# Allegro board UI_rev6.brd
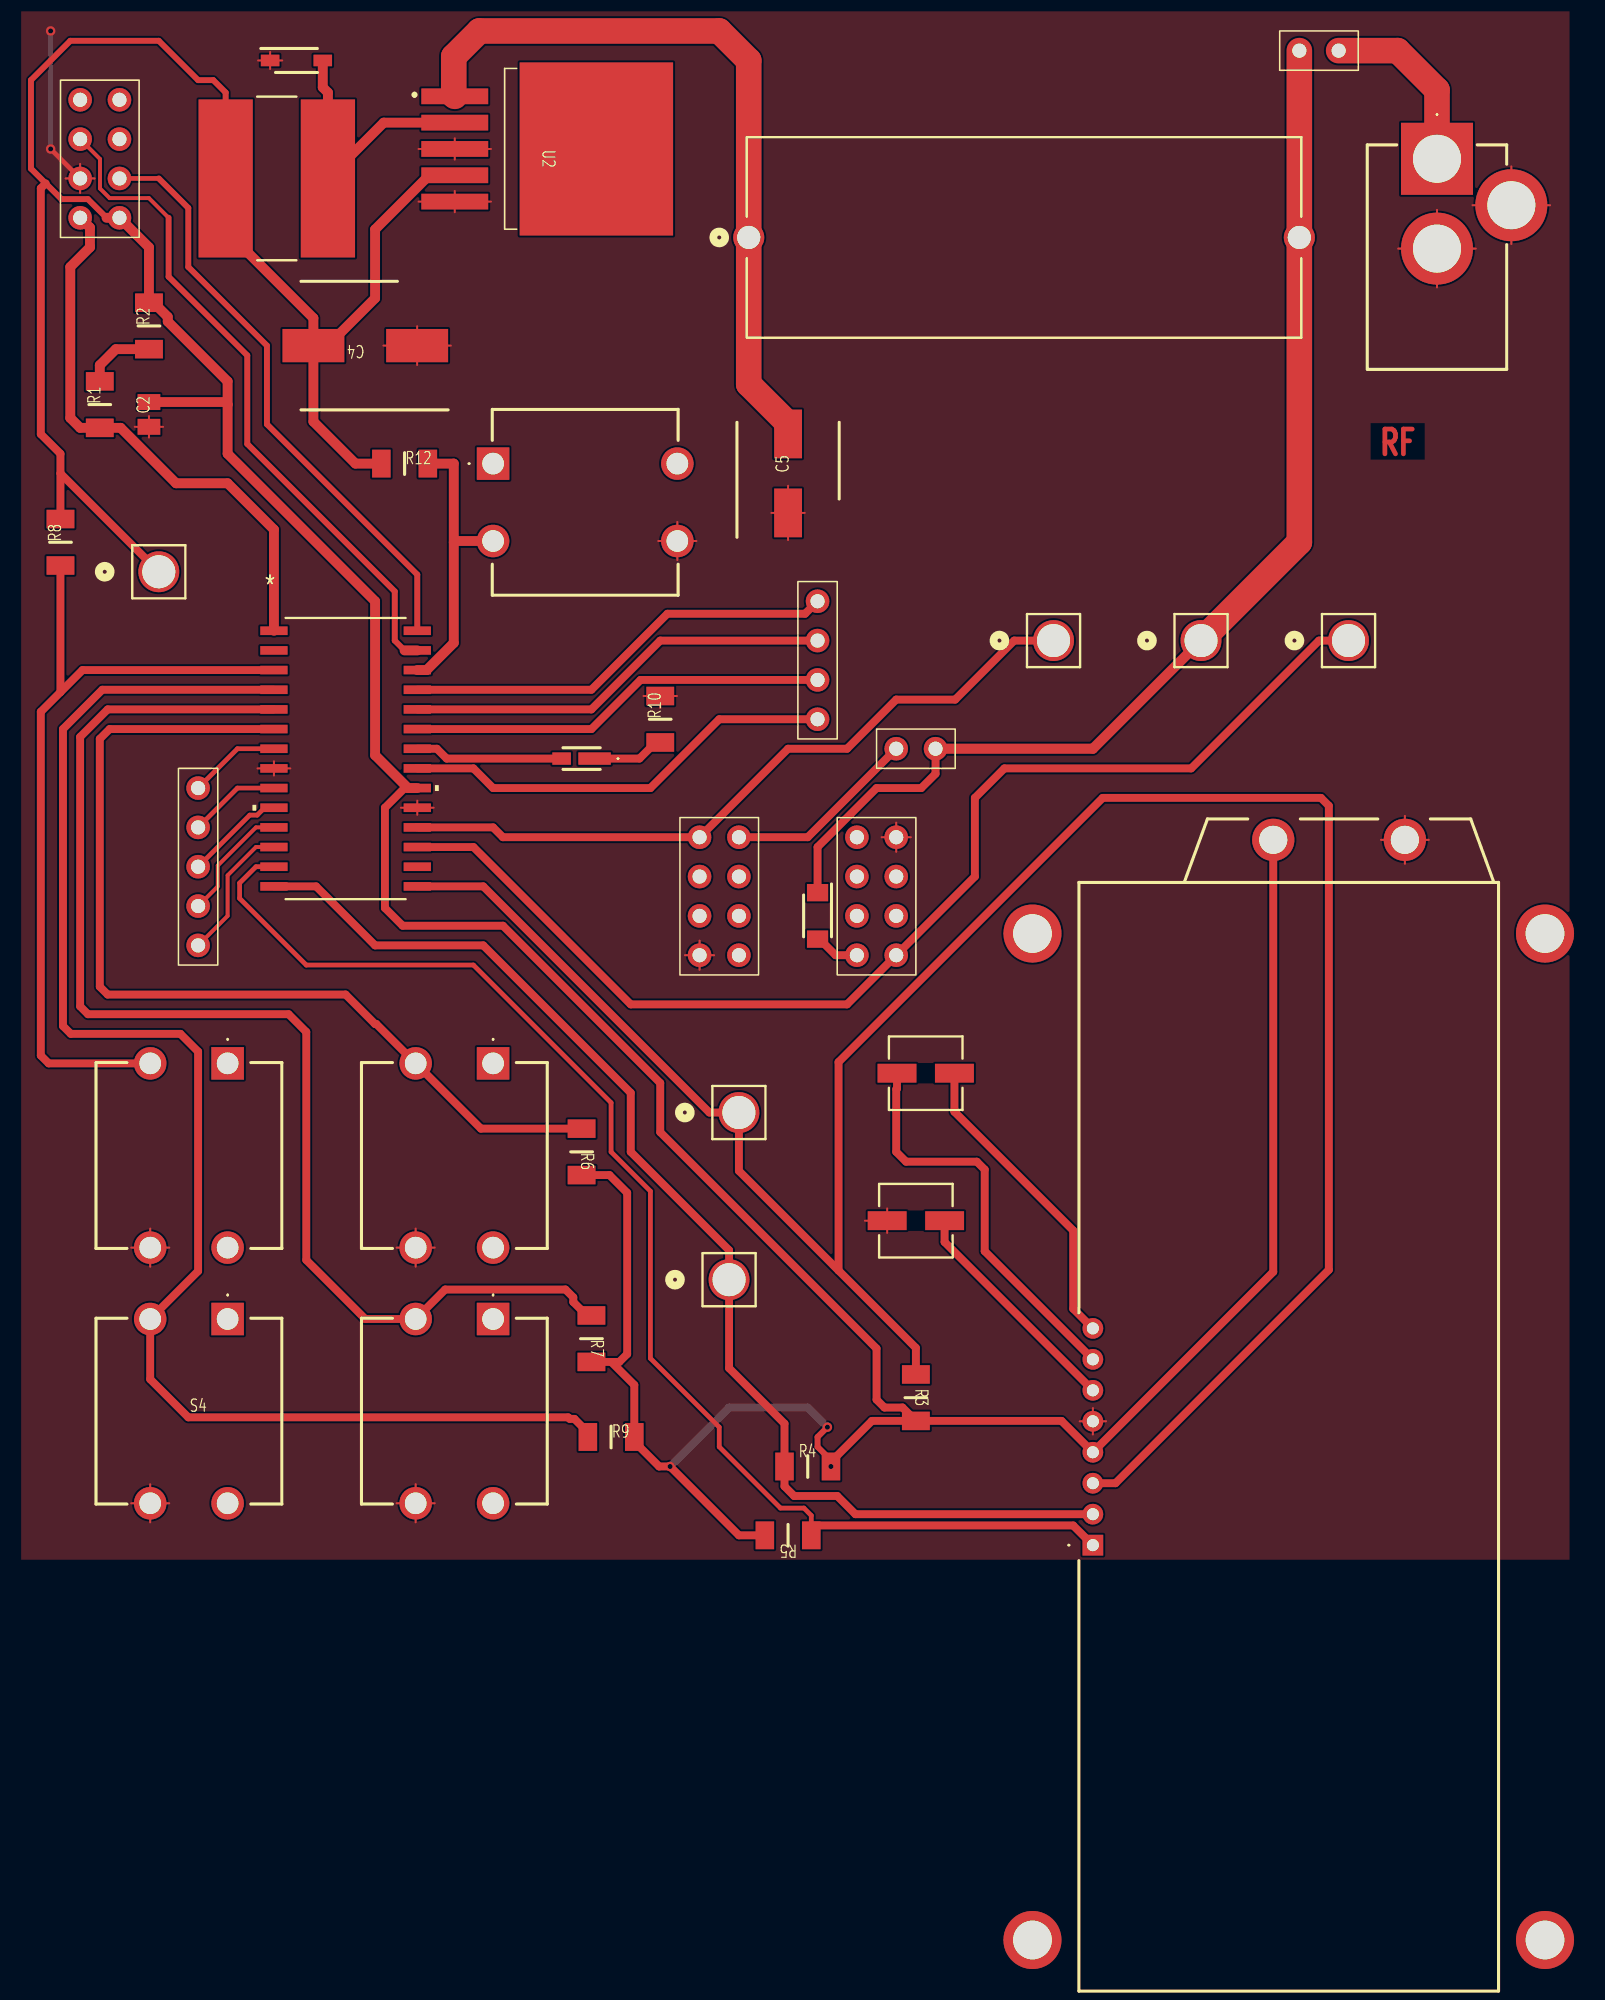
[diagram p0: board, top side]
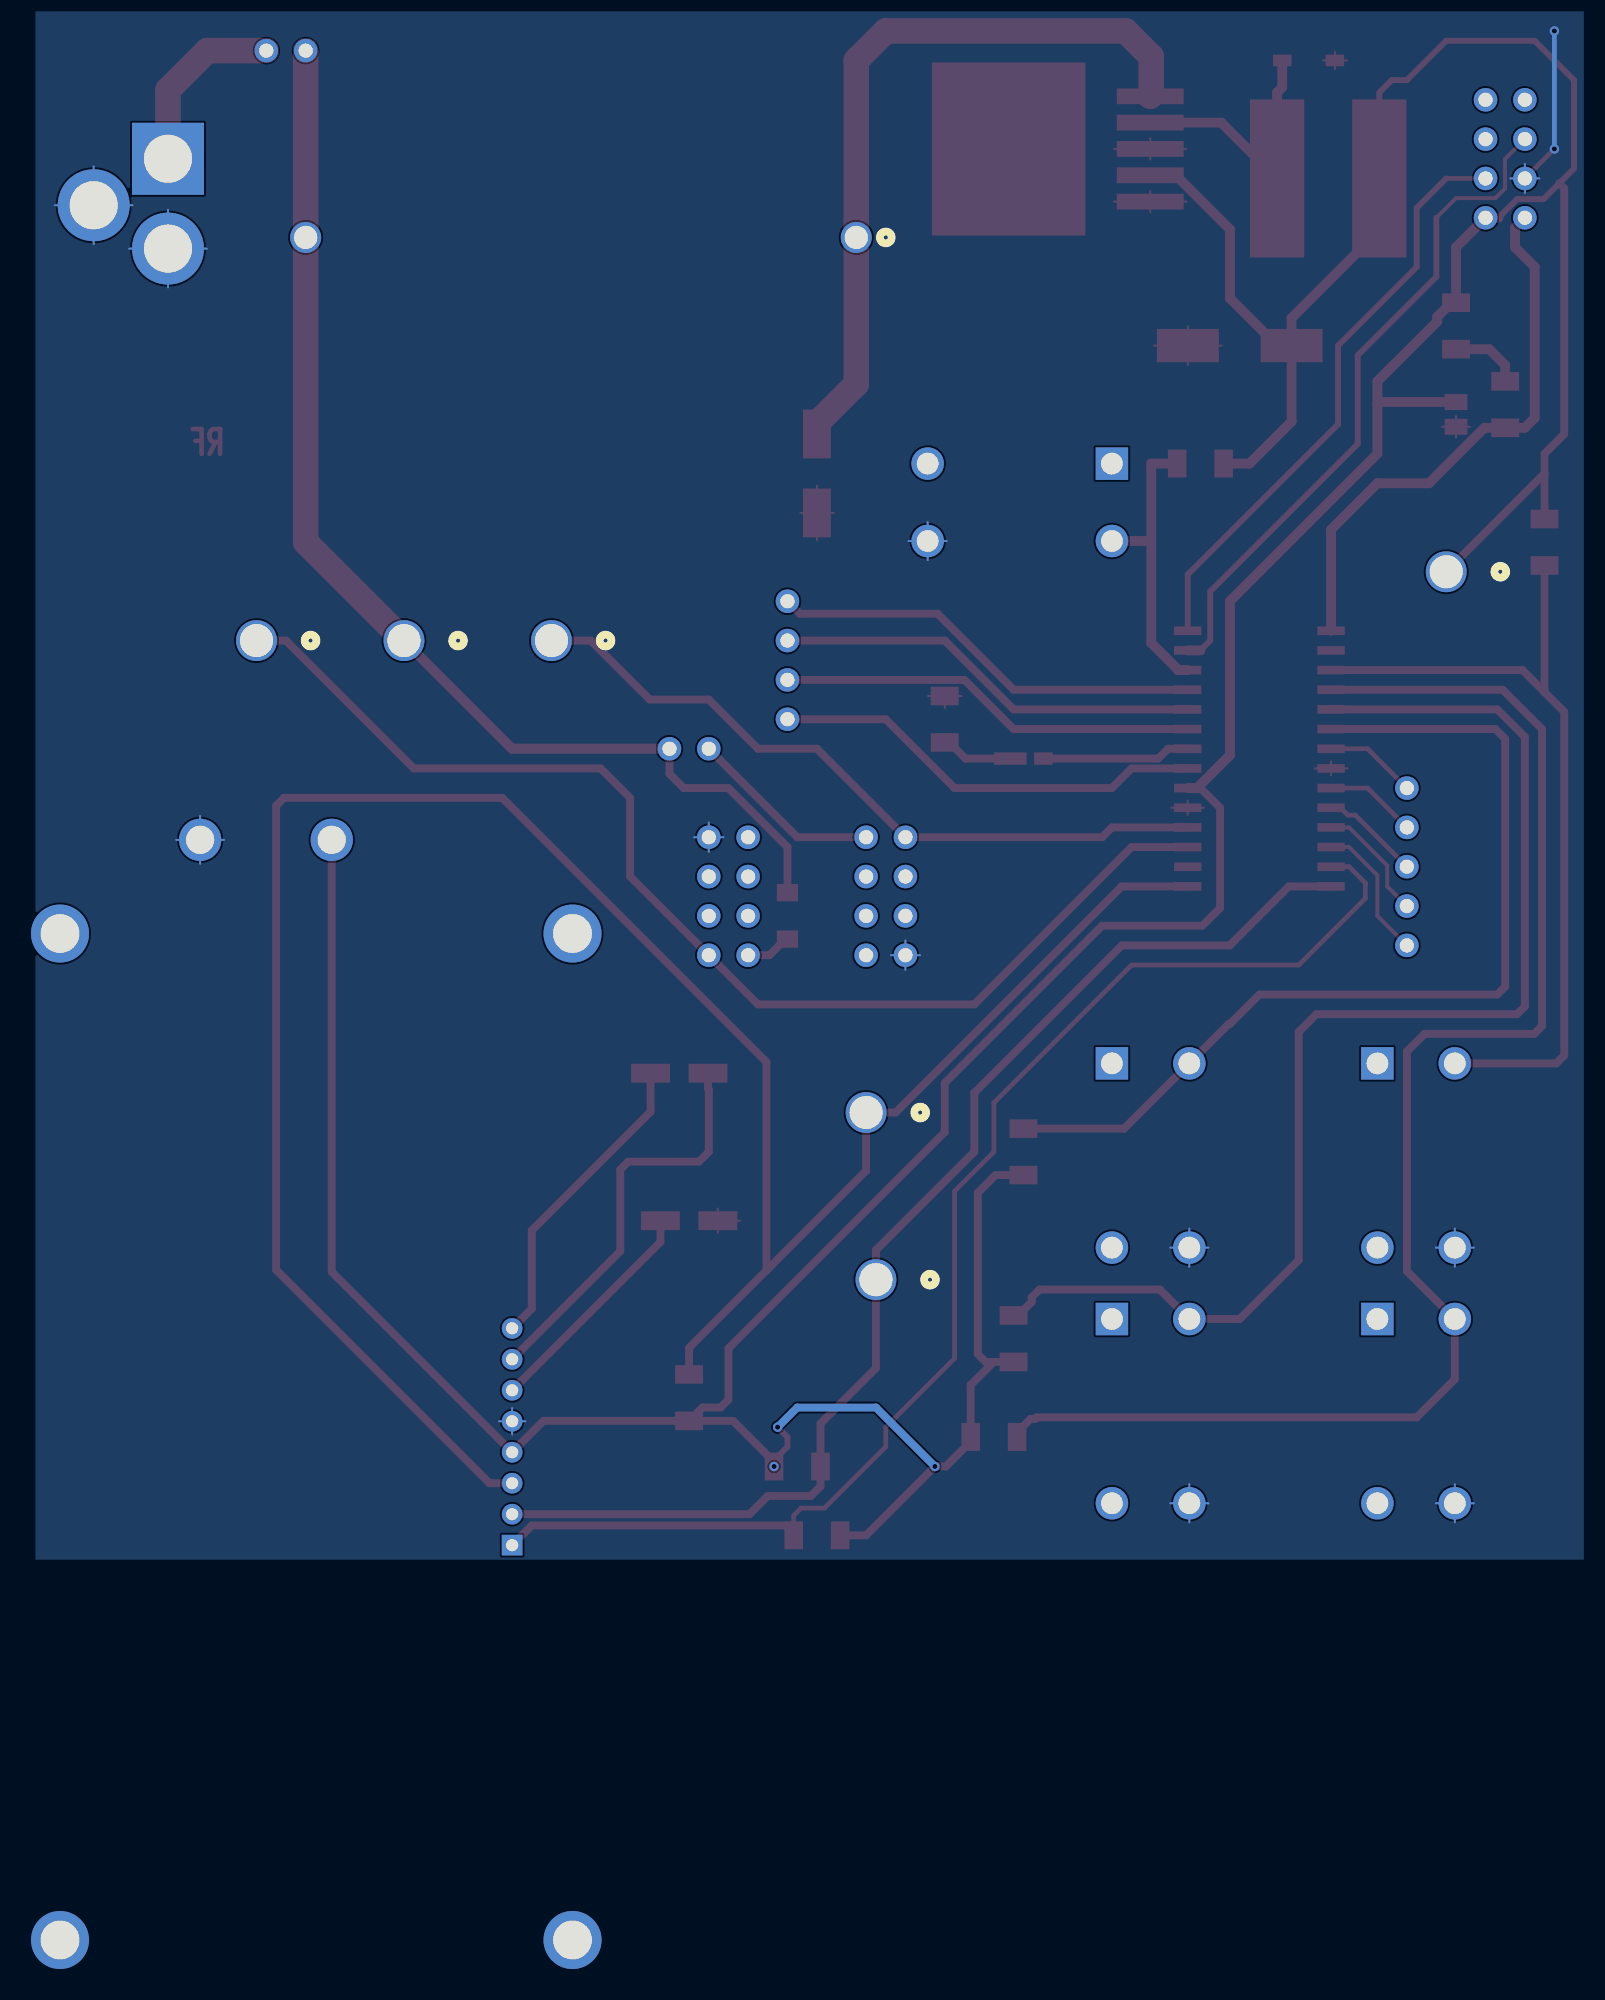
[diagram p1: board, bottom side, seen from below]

No outline. copper layers: TOP, BOTTOM. Coordinates in mm from the lowest, leftmost part position.

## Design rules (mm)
constraint set DEFAULT: min track width 0.127

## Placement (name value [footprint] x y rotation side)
C1  1uF  [CAP_WCAP-ASLI_04P0X05P5_WRE]  55.25 20.95 0 top
C2  0.1uF  [CAPC2012X147N]  5.71 73.02 90 top
C3  1uF  [CAP_WCAP-ASLI_04P0X05P5_WRE]  55.88 30.48 0 top
C4  330uF  [CAPAE830X1050N]  19.69 77.47 180 top
C5  100uF  [CAPAE660X770N]  46.99 69.21 90 top
D1  1N5819  [SOD3716X145N]  15.24 95.88 0 top
D2  LED  [T1341NB30C000112U1930]  33.65 50.8 270 top
D3  SBR3U40S1F-7  [SODFL3518X115N]  48.89 40.64 270 top
DS1  NHD-C0220BIZ-FSW-FBW-3V3M  [NHDC0220BIZFSWFBW3V3M]  66.68 0 270 top
F1  500mA  [FUSE_354101-GY_LTF]  44.45 84.45 0 top
J2  8 HEADER- Snapmaker Debugger  [JUMPER8]  1.27 85.72 0 top
J4  Daisy In  [JUMPER8]  43.81 45.72 180 top
J5  Daisy Out  [JUMPER8]  51.44 38.1 0 top
J6  CON4  [JUMPER4]  48.89 53.34 90 top
J8  JUMPER  [JUMPER2]  56.51 51.44 180 top
J9  JUMPER  [JUMPER2]  80.01 96.52 0 top
J10  CON5  [JUMPER5]  8.89 48.89 270 top
L1  220 uH  [IND_BOURNS_SRN1060]  13.97 88.26 0 top
P1  CONN JACK PWR  [694108301002]  88.9 89.53 90 top
R1  220  [RESC3216X75N]  2.54 73.66 90 top
R2  1K  [RESC3216X75N]  5.71 78.74 90 top
R3  10K  [RESC3216X75N]  55.25 9.52 270 top
R4  10K  [RESC3216X75N]  48.26 5.08 0 top
R5  10K  [RESC3216X75N]  46.99 0.63 180 top
R6  10K  [RESC3216X75N]  33.65 25.4 270 top
R7  10K  [RESC3216X75N]  34.29 13.33 270 top
R8  10K  [RESC3216X75N]  0 64.77 90 top
R9  10K  [RESC3216X75N]  35.56 6.98 0 top
R10  1K  [RESC3216X75N]  38.73 53.34 90 top
R12  10K  [RESC3216X75N]  22.22 69.85 0 top
S1  PRT-14460  [PRT14460]  10.79 31.11 0 top
S2  PRT-14460  [PRT14460]  27.94 14.6 0 top
S3  PRT-14460  [PRT14460]  27.94 31.11 0 top
S4  PRT-14460  [PRT14460]  10.79 14.6 0 top
S6  PRT-14460  [PRT14460]  27.94 69.85 90 top
TP1  TEST POINT  [CONN1_5011_KEY]  6.35 62.86 0 top
TP2  TEST POINT  [CONN1_5011_KEY]  73.66 58.42 0 top
TP3  TEST POINT  [CONN1_5011_KEY]  43.81 27.94 0 top
TP4  TEST POINT  [CONN1_5011_KEY]  43.18 17.14 0 top
TP5  TEST POINT  [CONN1_5011_KEY]  83.19 58.42 0 top
TP6  TEST POINT  [CONN1_5011_KEY]  64.13 58.42 0 top
U2  LM2575-3P3WU-TR  [MIC29302WU]  37.46 90.17 270 top
U3  PIC18F27Q10-SPSOSS  [SOIC28_SO_MCH]  18.41 50.8 0 top

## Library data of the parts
C1 C3 = C: User Part Number: PN; Tolerance: TOL
C2 C4 C5 = C
D1 = DIODE SCHOTTKY
D2 = LED
D3 = SBR3U40S1F-7
DS1 = NHD-C0220BIZ-FSW-FBW-3V3M
F1 = FUSE: User Part Number: PN; Tolerance: TOL
J2 = 8 HEADER: User Part Number: ***
J4 J5 = CON8: User Part Number: ***
J6 = CON4: User Part Number: ***
J8 J9 = JUMPER: User Part Number: ***
J10 = CON5: User Part Number: ***
L1 = INDUCTOR: User Part Number: PN; Tolerance: TOL
P1 = CONN JACK PWR
R1-R10 R12 = RESISTOR
S1-S4 S6 = PRT-14460
TP1-TP6 = TEST POINT: User Part Number: PN; Tolerance: TOL
U2 = LM2575-3P3WU-TR_2
U3 = PIC18F27Q10T-ISO: User Part Number: PN; Tolerance: TOL

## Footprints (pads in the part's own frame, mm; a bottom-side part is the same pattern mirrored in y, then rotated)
694108301002
  rect 4.65x4.65 hole 3.1: 1(0,0)
  round 4.65 hole 3.1: 2(-5.8,0) 3(-3,-4.8)
CAP_WCAP-ASLI_04P0X05P5_WRE
  rect 2.515x1.219 smd: 1(-1.854,0) 2(1.854,0)
CAPAE660X770N
  rect 3.15x1.8 smd: 1(-2.55,0) 2(2.55,0)
CAPAE830X1050N
  rect 4x2.15 smd: 1(-3.35,0) 2(3.35,0)
CAPC2012X147N
  rect 1.03x1.47 smd: 1(-0.8,0) 2(0.8,0)
CONN1_5011_KEY
  round 2.642 hole 2.134: 1(0,0)
FUSE_354101-GY_LTF
  round 2.007 hole 1.499: 1(0,0) 2(35.56,0)
IND_BOURNS_SRN1060
  rect 3.505x10.211 smd: 1(-3.302,0) 2(3.302,0)
JUMPER2
  round 1.524 hole 0.914: 1(0,0) 2(2.54,0)
JUMPER4
  round 1.524 hole 0.914: 1(0,0) 2(2.54,0) 3(5.08,0) 4(7.62,0)
JUMPER5
  round 1.524 hole 0.914: 1(0,0) 2(2.54,0) 3(5.08,0) 4(7.62,0) 5(10.16,0)
JUMPER8
  round 1.524 hole 0.914: 1(0,0) 2(2.54,0) 3(0,2.54) 4(2.54,2.54) 5(0,5.08) 6(2.54,5.08) 7(0,7.62) 8(2.54,7.62)
MIC29302WU
  rect 1.02x4.32 smd: 1(-3.4,-12) 2(-1.7,-12) 3(0,-12) 4(1.7,-12) 5(3.4,-12)
  rect 11.18x9.91 smd: 6(0,-2.855)
NHDC0220BIZFSWFBW3V3M
  rect 1.337x1.337 hole 0.78: 1(0,0)
  round 1.337 hole 0.78: 2(-2,0) 3(-4,0) 4(-6,0) 5(-8,0) 6(-10,0) 7(-12,0) 8(-14,0)
  round 2.73 hole 1.82: 9(-45.55,20.15) 10(-45.55,11.65)
  round 3.75 hole 2.5: 11(25.5,-3.9) 12(-39.5,-3.9) 13(25.5,29.2) 14(-39.5,29.2)
PRT14460
  rect 2.1x2.1 hole 1.4: 1(0,0)
  round 2.1 hole 1.4: 2(0,-11.9) 3(-5,0) 4(-5,-11.9)
RESC3216X75N
  rect 1.2x1.8 smd: 1(-1.5,0) 2(1.5,0)
SOD3716X145N
  rect 1.2x0.75 smd: 1(-1.7,0) 2(1.7,0)
SODFL3518X115N
  rect 1.12x1.37 smd: 1(-1.5,0) 2(1.5,0)
SOIC28_SO_MCH
  rect 1.765x0.559 smd: 1(-4.629,8.255) 2(-4.629,6.985) 3(-4.629,5.715) 4(-4.629,4.445) 5(-4.629,3.175) 6(-4.629,1.905) 7(-4.629,0.635) 8(-4.629,-0.635) 9(-4.629,-1.905) 10(-4.629,-3.175) 11(-4.629,-4.445) 12(-4.629,-5.715) 13(-4.629,-6.985) 14(-4.629,-8.255) 15(4.629,-8.255) 16(4.629,-6.985) 17(4.629,-5.715) 18(4.629,-4.445) 19(4.629,-3.175) 20(4.629,-1.905) 21(4.629,-0.635) 22(4.629,0.635) 23(4.629,1.905) 24(4.629,3.175) 25(4.629,4.445) 26(4.629,5.715) 27(4.629,6.985) 28(4.629,8.255)
T1341NB30C000112U1930
  rect 0.8x2.1 smd: 1(0,0.84)
  rect 0.8x1.2 smd: 2(0,-1.29)

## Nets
+3.3V: C2.2 C4.2 DS1.4(VSS) DS1.10 J2.2 L1.1 R2.2 R3.2 R4.2 R5.2 R6.2 R7.2 R8.2 R9.2 R12.1 TP1.1 U2.4 U3.20
GND: C1.1 C2.1 C4.1 C5.1 D1.1 DS1.5 DS1.9 J2.3 J4.8 J5.8 P1.2 P1.3 R10.2 S1.4 S2.4 S3.4 S4.4 S6.4 U2.3 U2.5 U3.8 U3.19(VSS_2)
ICSPCLK: J2.5 U3.27
ICSPDAT: J2.4 U3.28
LEFTBUTTON: R6.1 S3.3 U3.6
MCLR: J2.1 R1.1 U3.1
PWR IN: J4.1 J8.2
PWR OUT: D3.1(K) F1.2 J8.1 J9.1 TP2.1
RA5: J10.1 U3.7
RA6: J10.3 U3.10
RA7: J10.2 U3.9
RB0: J6.1 U3.21
RB2: J6.2 U3.23
RB3: J6.3 U3.24
RB4: J6.4 U3.25
RB5: R12.2 S6.3 U3.26
RC0: J10.4 U3.11
RC1: J10.5 U3.12
RIGHTBUTTON: R7.1 S2.3 U3.5
RST: DS1.1 R5.1 U3.13
RX: J4.2 TP6.1 U3.18
SCL: DS1.2 R4.1 TP4.1 U3.14
SDA: DS1.3 R3.1 TP3.1 U3.15
SELECT1: R8.1 S1.3 U3.3
SELECT2: R9.1 S4.3 U3.4
TX: J5.2 TP5.1 U3.17
N01597: R1.2 R2.1
N05849: D1.2(CATHODE) L1.2 U2.2
N06927: C5.2 F1.1 U2.1(VIN)
N30188: D2.1(CATHODE) R10.1
N40798: C1.2 DS1.6
N40848: C3.1 DS1.7
N40866: C3.2 DS1.8
N41411: J9.2 P1.1
N115890: D2.2 U3.22
N187930: D3.2 J5.1

Pads without a net: DS1 11 12 13 14; J2 6 7 8; J4 3 4 5 6 7; J5 3 4 5 6 7; S1 1 2; S2 1 2; S3 1 2; S4 1 2; S6 1 2; U2 6; U3 2 16

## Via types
v1: diameter 0.61, hole 0.33, TOP to BOTTOM, 5 vias

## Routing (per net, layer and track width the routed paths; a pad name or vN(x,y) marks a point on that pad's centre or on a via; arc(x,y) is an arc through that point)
+3.3V: length 326.9
  TOP w0.381: 2.98,85.72 1.77,86.93 0.06,86.93 -1.91,88.9 -1.91,94.62 0.63,97.15 6.35,97.15 8.89,94.62 9.87,94.62 10.67,93.81 L1.1 ; 49.76,5.38 49.76,5.48 48.89,6.35 48.89,6.98 v1(49.53,7.62)
  TOP w0.508: R3.2 54.38,8.89 53.21,8.89 52.7,9.4 52.7,12.7 38.73,26.67 38.73,29.84 28.57,40 22.1,40 20.95,41.15 20.95,47.62 22.22,48.89 22.44,48.89 ; R3.2 64.65,8.02 DS1.4 78.32,17.65 DS1.10 ; R3.2 52.4,8.02 49.76,5.38 v1(49.76,5.08) ; R7.2 35.57,11.83 ; 35.57,11.83 36.09,11.83 36.6,12.34 36.6,22.76 35.46,23.9 R6.2 ; 35.57,11.83 37.06,10.35 R9.2 37.06,6.68 38.66,5.08 v1(39.37,5.08) 43.81,0.63 R5.2 ; -0.95,87.95 -1.27,87.63 -1.27,71.75 0,70.48 0,69.21 ; 0,69.21 R8.2 ; 0,69.21 TP1.1
  TOP w0.635: C4.2 16.33,79.25 10.67,84.91 L1.1 ; C4.2 16.33,72.56 19.05,69.85 R12.1 ; C4.2 17.26,77.47 20.32,80.53 20.32,84.97 23.81,88.47 U2.4 ; 2.98,85.72 J2.2 5.71,83.82 R2.2 6.02,80.24 6.93,79.33 6.93,79.03 10.79,75.16 10.79,73.66 ; C2.2 10.63,73.83 10.79,73.66 ; U3.20 22.44,48.89 20.32,51.02 20.32,60.96 10.79,70.48 10.79,73.66
  BOTTOM w0.508: v1(39.37,5.08) 43.18,8.89 48.26,8.89 v1(49.53,7.62)
GND: length 183.7
  TOP w0.127: U2.3 25.46,90.86 ; U2.3 27.8,90.17 ; U2.3 23.13,90.17 ; U2.3 25.46,89.48 ; 91.2,86.53 P1.3 ; P1.3 96.2,86.53 ; P1.3 93.7,89.04 ; P1.3 93.7,84.03 ; 22.94,17.99 S3.4 ; S3.4 22.94,20.44 ; S3.4 24.17,19.22 ; S3.4 21.71,19.22 ; 21.71,2.71 S2.4 ; S2.4 22.94,3.93 ; S2.4 22.94,1.48 ; S2.4 24.17,2.71 ; 4.8,72.22 C2.1 ; C2.1 5.71,72.92 ; C2.1 6.63,72.22 ; C2.1 5.71,71.53 ; C4.1 25.21,77.47 ; C4.1 23.03,78.72 ; C4.1 23.03,76.22 ; C4.1 20.86,77.47 ; 39.84,63.62 S6.4 ; S6.4 41.07,64.85 ; S6.4 39.84,66.08 ; S6.4 38.61,64.85 ; 40.33,38.1 J4.8 ; J4.8 41.27,37.16 ; J4.8 41.27,39.04 ; J4.8 42.21,38.1 ; 25.46,86.08 U2.5 ; U2.5 23.13,86.77 ; U2.5 27.8,86.77 ; U2.5 25.46,87.46 ; 86.83,44.01 DS1.9 ; DS1.9 85.28,45.55 ; DS1.9 86.83,47.09 ; DS1.9 88.37,45.55 ; S4.4 5.79,3.93 ; S4.4 4.57,2.71 ; S4.4 7.02,2.71 ; S4.4 5.79,1.48 ; R10.2 39.81,54.84 ; R10.2 37.66,54.84 ; R10.2 38.73,54.06 ; 13.54,95.88 13.54,96.44 ; 13.54,95.88 14.32,95.88 ; 13.54,95.88 12.76,95.88 ; 13.54,95.88 13.54,95.33 ; 0.33,88.26 J2.3 ; J2.3 1.27,87.32 ; J2.3 1.27,89.2 ; J2.3 2.21,88.26 ; 53.03,45.72 J5.8 ; J5.8 53.97,46.66 ; J5.8 54.91,45.72 ; J5.8 53.97,44.78 ; DS1.5 66.68,8.85 ; DS1.5 65.83,8 ; DS1.5 67.52,8 ; DS1.5 66.68,7.15 ; U3.8 13.79,50.62 ; U3.8 12.73,50.16 ; U3.8 13.79,49.71 ; U3.8 14.85,50.16 ; P1.2 88.9,86.24 ; P1.2 86.4,83.73 ; P1.2 88.9,81.23 ; P1.2 91.4,83.73 ; 51.96,20.95 C1.1 ; C1.1 53.39,20.17 ; C1.1 53.39,21.74 ; S1.4 5.79,20.44 ; S1.4 7.02,19.22 ; S1.4 5.79,17.99 ; S1.4 4.57,19.22 ; 45.91,66.67 C5.1 ; C5.1 46.99,64.91 ; C5.1 46.99,68.42 ; C5.1 48.07,66.67 ; U3.19 24.1,47.62 ; U3.19 23.04,47.17 ; U3.19 21.98,47.62 ; U3.19 23.04,48.08
  TOP w0.305: v1(-0.63,90.17) J2.3
  BOTTOM w0.127: 86.83,44.01 DS1.9 ; DS1.9 88.37,45.55 ; DS1.9 85.28,45.55 ; DS1.9 86.83,47.09 ; 22.94,1.48 S2.4 ; S2.4 21.71,2.71 ; S2.4 22.94,3.93 ; S2.4 24.17,2.71 ; DS1.5 66.68,8.85 ; DS1.5 66.68,7.15 ; DS1.5 65.83,8 ; DS1.5 67.52,8 ; J4.8 41.27,39.04 ; J4.8 42.21,38.1 ; J4.8 41.27,37.16 ; J4.8 40.33,38.1 ; J2.3 2.21,88.26 ; J2.3 1.27,89.2 ; J2.3 1.27,87.32 ; J2.3 0.33,88.26 ; P1.2 91.4,83.73 ; P1.2 88.9,86.24 ; P1.2 86.4,83.73 ; P1.2 88.9,81.23 ; S1.4 7.02,19.22 ; S1.4 5.79,20.44 ; S1.4 4.57,19.22 ; S1.4 5.79,17.99 ; 39.84,63.62 S6.4 ; S6.4 39.84,66.08 ; S6.4 41.07,64.85 ; S6.4 38.61,64.85 ; 22.94,17.99 S3.4 ; S3.4 24.17,19.22 ; S3.4 22.94,20.44 ; S3.4 21.71,19.22 ; 53.97,44.78 J5.8 ; J5.8 53.03,45.72 ; J5.8 54.91,45.72 ; J5.8 53.97,46.66 ; P1.3 93.7,89.04 ; P1.3 91.2,86.53 ; P1.3 93.7,84.03 ; P1.3 96.2,86.53 ; 5.79,1.48 S4.4 ; S4.4 7.02,2.71 ; S4.4 4.57,2.71 ; S4.4 5.79,3.93
  BOTTOM w0.305: v1(-0.63,97.79) v1(-0.63,90.17)
ICSPCLK: length 44
  TOP w0.254: 6.98,85.72 5.71,87 3.18,87 2.55,87.62 2.55,89.52 J2.5
  TOP w0.381: 22.22,57.78 21.59,58.42 21.59,61.59 12.06,71.12 12.06,76.83 6.98,81.91 6.98,85.72
  TOP w0.635: U3.27 22.22,57.78
ICSPDAT: length 38.7
  TOP w0.305: J2.4 6.35,88.26
  TOP w0.381: U3.28 23.04,62.68 13.33,72.39 13.33,77.47 8.25,82.55 8.25,86.36 6.35,88.26
LEFTBUTTON: length 62.4
  TOP w0.508: R6.1 27.15,26.9 S3.3 20.4,33.66 20.32,33.66 18.41,35.56 3.05,35.56 2.54,36.07 2.54,52.07 3.18,52.7 U3.6
MCLR: length 36.4
  TOP w0.635: J2.1 1.9,85.09 1.9,83.82 0.63,82.55 0.63,72.79 1.27,72.16 R1.1 3.88,72.16 7.46,68.58 10.79,68.58 13.79,65.59 U3.1
PWR IN: length 12.5
  TOP w0.508: J4.1 48.26,45.72 J8.2
PWR OUT: length 74.9
  TOP w0.508: J8.1 56.51,49.82 55.59,48.89 52.7,48.89 48.89,45.08 D3.1
  TOP w0.65: TP2.1 66.68,51.44 J8.1
  TOP w1.651: J9.1 F1.2 80.01,64.77 TP2.1
RA5: length 5.9
  TOP w0.305: J10.1 11.43,51.44 13.79,51.44
RA6: length 6.5
  TOP w0.305: U3.10 13.18,47.62 12.71,47.15 12.22,47.15 8.89,43.81
RA7: length 5.9
  TOP w0.305: J10.2 11.43,48.89 U3.9
RB0: length 28.2
  TOP w0.508: J6.1 42.54,53.34 38.1,48.89 27.94,48.89 26.67,50.16 U3.21
RB2: length 27.2
  TOP w0.508: J6.2 37.46,55.88 34.29,52.7 U3.23
RB3: length 27.7
  TOP w0.508: U3.24 34.29,53.97 38.73,58.42 J6.3
RB4: length 28.2
  TOP w0.508: J6.4 48.09,60.15 39.2,60.15 34.29,55.24 U3.25
RB5: length 18.9
  TOP w0.508: 25.48,64.85 25.4,64.77
  TOP w0.635: U3.26 23.65,56.51 25.4,58.27 25.4,69.85 R12.2 ; S6.3 25.48,64.85
RC0: length 7.8
  TOP w0.254: J10.4 10.16,42.54 10.16,43.89 12.62,46.35 U3.11
RC1: length 9.1
  TOP w0.254: U3.12 12.62,45.08 10.79,43.26 10.79,40.64 J10.5
RIGHTBUTTON: length 82.3
  TOP w0.508: U3.5 3.05,53.97 1.27,52.2 1.27,34.8 1.78,34.29 14.73,34.29 15.88,33.15 15.88,18.41 19.69,14.6 S2.3 24.84,16.51 32.62,16.51 33.12,16 33.12,15.7 33.99,14.84 R7.1
RST: length 86
  TOP w0.305: 13.79,43.81 12.62,43.81 11.57,42.76 11.57,41.77 15.88,37.46 26.67,37.46 35.56,28.57 35.56,25.4 38.1,22.86 38.1,12.06 42.54,7.62 42.54,6.35 46.5,2.39 48.01,2.39 48.49,1.92 48.49,1.27
  TOP w0.508: DS1.1 65.4,1.27 48.49,1.27 R5.1
RX: length 46.6
  TOP w0.508: U3.18 27.94,46.35 28.57,45.72 J4.2 46.99,51.44 50.8,51.44 53.97,54.61 57.78,54.61 61.59,58.42 TP6.1
SCL: length 78.8
  TOP w0.508: DS1.2 51.34,2 50.16,3.17 47.38,3.17 46.76,3.8 R4.1 46.76,7.85 43.18,11.43 TP4.1 43.18,19.05 36.83,25.4 36.83,29.21 27.31,38.73 20.32,38.73 16.51,42.54 U3.14
SDA: length 151.8
  TOP w0.508: DS1.3 68.13,4 81.91,17.78 81.91,47.75 81.41,48.26 67.31,48.26 50.25,31.2 50.25,17.74 ; 50.25,17.74 55.25,12.74 R3.1 ; 50.25,17.74 43.81,24.17 TP3.1 41.91,27.94 27.31,42.54 U3.15
SELECT1: length 53.8
  TOP w0.508: S1.3 -0.76,31.11 -1.27,31.62 -1.27,53.82 0,55.09 ; 0,55.09 R8.1 ; 0,55.09 1.42,56.51 U3.3
SELECT2: length 95.7
  TOP w0.508: R9.1 34.06,7.29 33.19,8.15 32.89,8.15 32.79,8.25 8.25,8.25 5.79,10.71 S4.3 8.89,17.7 8.89,31.88 7.75,33.02 0.67,33.02 0.16,33.53 0.16,52.7 2.7,55.24 U3.4
TX: length 77.1
  TOP w0.508: U3.17 26.67,45.08 36.83,34.92 50.8,34.92 J5.2 59.06,43.18 59.06,48.26 60.96,50.16 73.02,50.16 81.28,58.42 TP5.1
N01597: length 4.6
  TOP w0.635: R2.1 3.58,77.24 2.54,76.2 R1.2
N05849: length 17.4
  TOP w0.635: D1.2 16.94,94.15 17.27,93.81 L1.2 20.88,91.87 U2.2
N06927: length 48.3
  TOP w1.651: C5.2 46.99,72.44 44.45,74.98 F1.1 44.45,95.88 42.54,97.79 27.05,97.79 25.4,96.14 25.4,93.64 U2.1
N30188: length 4.7
  TOP w0.508: R10.1 38.43,51.84 37.39,50.8 D2.1
N40798: length 14.9
  TOP w0.508: DS1.6 57.1,19.58 C1.2
N40848: length 26.4
  TOP w0.508: C3.1 54.03,29.49 53.97,29.44 53.97,25.4 54.61,24.76 59.18,24.76 59.69,24.26 59.69,18.98 DS1.7
N40866: length 20.2
  TOP w0.508: C3.2 57.73,27.99 65.4,20.32 65.4,15.27 DS1.8
N41411: length 11.8
  TOP w1.651: J9.2 86.36,96.52 88.9,93.98 P1.1
N115890: length 9.6
  TOP w0.508: 23.04,51.44 24.31,51.44 24.94,50.8 D2.2
N187930: length 3
  TOP w0.508: J5.1 50.06,38.1 49.02,39.14 D3.2

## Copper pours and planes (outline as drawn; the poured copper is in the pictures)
GND on TOP: 97.46,-0.94 97.46,99.06 -2.54,99.06 -2.54,-0.94
GND on BOTTOM: 97.46,-0.94 97.46,99.06 -2.54,99.06 -2.54,-0.94

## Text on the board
TOP: RF
